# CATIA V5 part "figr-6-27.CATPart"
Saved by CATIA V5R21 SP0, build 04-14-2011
Part number: Part1
Bounding box of the stored display mesh (mm): x -150 to 0, y -70 to 60, z -20 to 40
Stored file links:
  D:\CATIAV5R21-WORK\c06_cat_v5r21\catia-files\FIGURE-6-27.CATPart
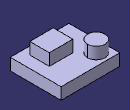
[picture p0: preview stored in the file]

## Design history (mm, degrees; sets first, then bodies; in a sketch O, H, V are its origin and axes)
Body1 (main body)
  Sketch1 on yz-plane, origin (0, 0, 0), H (0, 1, 0), V (0, 0, 1)
    line L1 (-70, 10) -> (60, 10)
    line L2 (60, 10) -> (60, -20)
    line L3 (60, -20) -> (-70, -20)
    line L4 (-70, -20) -> (-70, 10)
    horizontal: L1 H, L3 H
    vertical: L2 V, L4 V
  Pad1: profile Sketch1, direction (-1, 0, 0), length 150
  Sketch2 on face of Pad1 from Sketch1.L1, origin (0, 0, 10), H (1, 0, 0), V (0, 1, 0)
    circle A1 centre (-120, 30) radius 22.3607
  Pad2: profile Sketch2, direction (0, 0, 1), length 30
  Sketch3 on face of Pad1 from Sketch1.L1, origin (0, 0, 10), H (1, 0, 0), V (0, 1, 0)
    point P1 (-90, 0)
    line L1 (-90, 0) -> (-30, 0)
    line L2 (-30, 0) -> (-30, -50)
    line L3 (-30, -50) -> (-90, -50)
    line L4 (-90, -50) -> (-90, 0)
    coincidence: P1 H
    horizontal: L1 H, L3 H
    vertical: L2 V, L4 V
  Pad3: profile Sketch3, direction (0, 0, 1), length 30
